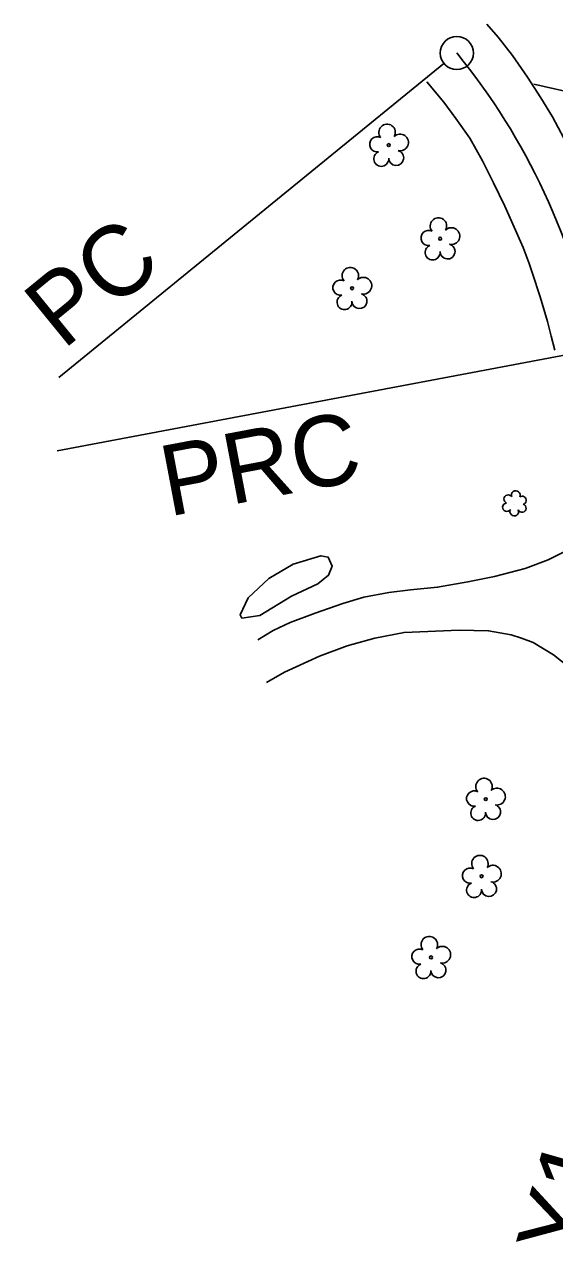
# Model space of a CAD drawing. Extents: x 479429 to 482809, y 488118 to 492379.
# Drawn here: x 481001.5 to 481121.6, y 490861 to 491136.5 of the extents above; entities that cross this region are included whole.
import ezdxf

# ---------------------------------------------------------------- set-up
doc = ezdxf.new("R2010")
doc.units = 0
for name, color, linetype in [('CTL Secondary Horizontal and Vertical Text', 7, 'Continuous'), ('Exist Horizontal Alignment', 7, 'Continuous'), ('Exist Other Culture Area Outline', 7, 'Continuous'), ('Exist Roads EOP', 7, 'Continuous'), ('Exist Roads EOP Other', 7, 'Continuous'), ('Exist Roads Soil', 7, 'Continuous'), ('Exist Vegetation Shrub CELL', 7, 'Continuous'), ('Exist Vegetation Tree CELL', 7, 'Continuous')]:
    doc.layers.add(name, color=color, linetype=linetype)

msp = doc.modelspace()

# ---------------------------------------------------------------- linework, layer by layer
at = {"layer": 'Exist Horizontal Alignment'}
for p, q in [((481096.5, 491127.64), (481009.35, 491056.54)), ((481126.93, 491062.26), (481008.98, 491039.95))]:
    msp.add_line(p, q, dxfattribs=at)
msp.add_circle((481099.4, 491130.01), 3.75, dxfattribs=at)
msp.add_arc((480982.98, 491035.04), 150.25, 10.7112, 39.2065, dxfattribs=at)
at = {"layer": 'Exist Other Culture Area Outline'}
msp.add_lwpolyline([(481050.74, 491002.12), (481054.81, 491002.71), (481062, 491007.11), (481067.93, 491009.89), (481070.39, 491011.8), (481071.17, 491013.86), (481070.32, 491015.9), (481068.66, 491016.25), (481062.35, 491014.35), (481056.83, 491011.06), (481052.16, 491006.67), (481050.34, 491002.89), (481050.74, 491002.12)], dxfattribs=at)
at = {"layer": 'Exist Roads EOP'}
for points in [[(481106.2, 491136.5), (481108.79, 491133.61), (481112.05, 491129.43), (481115.42, 491124.55), (481118.46, 491119.89), (481121.04, 491115.59), (481123.64, 491110.73)], [(481121.63, 491062.76), (481120.8, 491065.9), (481119.9, 491069.23), (481118.24, 491074.84), (481116.55, 491080.1), (481115.77, 491082.39), (481114.41, 491086.02), (481112.12, 491091.28), (481110.25, 491095.36), (481107.69, 491100.66), (481105.2, 491105.64), (481102.33, 491110.73), (481099.21, 491115.21), (481096.44, 491118.92), (481092.61, 491123.52)]]:
    msp.add_lwpolyline(points, dxfattribs=at)
at = {"layer": 'Exist Roads EOP Other'}
for points in [[(481054.34, 490997.22), (481057.87, 490999.28), (481061.71, 491001.13), (481067.32, 491003.23), (481073.64, 491005.42), (481078.33, 491006.84), (481084.04, 491007.88), (481088.9, 491008.51), (481095.04, 491009.09), (481101.93, 491010.32), (481107.91, 491011.53), (481114.89, 491013.32), (481120.11, 491015.29), (481124.02, 491017.3), (481125.95, 491019.67), (481127.35, 491022.46), (481127.62, 491023.23), (481128.62, 491026.47)], [(481149.23, 490952.04), (481145.81, 490955.42), (481142.2, 490959.44), (481138.39, 490965.71), (481133.32, 490977.24), (481127.4, 490987.65), (481124.91, 490990.93), (481121.32, 490993.83), (481116.71, 490996.59), (481114.03, 490997.59), (481111.68, 490998.3), (481106.61, 490999.24), (481099.92, 490999.38), (481087.46, 490998.88), (481080.89, 490997.59), (481074.58, 490995.84), (481068.34, 490993.5), (481060.39, 490989.91), (481056.37, 490987.51)]]:
    msp.add_lwpolyline(points, dxfattribs=at)
at = {"layer": 'Exist Roads Soil'}
msp.add_lwpolyline([(481116.84, 491122.97), (481129.2, 491120.2), (481146.03, 491116.72), (481180.59, 491108.8), (481206.93, 491101.17)], dxfattribs=at)
at = {"layer": 'Exist Vegetation Shrub CELL'}
msp.add_line((481112.53, 491027.92), (481112.53, 491027.92), dxfattribs=at)
for centre, radius, start, end in [((481112.76, 491029.96), 0.99, 334.8391, 200.4717), ((481110.73, 491027.21), 0.955, 95.1099, 327.9534), ((481111.05, 491029.04), 0.968, 35.8908, 245.4216), ((481114.17, 491026.99), 0.937, 204.9913, 73.4601), ((481114.21, 491028.78), 0.929, 284.4567, 126.0861), ((481112.41, 491026.23), 0.984, 151.2797, 21.387)]:
    msp.add_arc(centre, radius, start, end, dxfattribs=at)
at = {"layer": 'Exist Vegetation Tree CELL'}
for p, q in [((481084.01, 491109.17), (481084.01, 491109.17)), ((481095.63, 491087.99), (481095.63, 491087.99)), ((481075.7, 491076.76), (481075.7, 491076.76)), ((481105.95, 490961.13), (481105.95, 490961.13)), ((481105.02, 490943.7), (481105.02, 490943.7)), ((481093.57, 490925.34), (481093.57, 490925.34))]:
    msp.add_line(p, q, dxfattribs=at)
for centre in [(481084.01, 491109.17), (481095.63, 491087.99), (481075.7, 491076.76), (481105.95, 490961.13), (481105.02, 490943.7), (481093.57, 490925.34)]:
    msp.add_circle(centre, 0.326, dxfattribs=at)
for centre, radius, start, end in [((481083.63, 491112.05), 1.86, 330.1651, 219.7134), ((481081.41, 491109.33), 1.73, 62.6636, 279.3457), ((481086.56, 491109.76), 1.9, 257.1011, 134.1999), ((481085.69, 491106.27), 1.7, 181.2822, 74.56), ((481082.31, 491106.05), 1.69, 111.5671, 6.231), ((481095.25, 491090.86), 1.86, 330.1651, 219.7134), ((481093.03, 491088.14), 1.73, 62.6636, 279.3457), ((481098.18, 491088.58), 1.9, 257.1011, 134.1999), ((481093.93, 491084.87), 1.69, 111.5671, 6.231), ((481097.31, 491085.09), 1.7, 181.2822, 74.56), ((481075.31, 491079.63), 1.86, 330.1651, 219.7134), ((481073.09, 491076.91), 1.73, 62.6636, 279.3457), ((481078.25, 491077.34), 1.9, 257.1011, 134.1999), ((481073.99, 491073.63), 1.69, 111.5671, 6.231), ((481077.37, 491073.86), 1.7, 181.2822, 74.56), ((481105.56, 490964.01), 1.86, 330.1651, 219.7134), ((481103.34, 490961.29), 1.73, 62.6636, 279.3457), ((481108.5, 490961.72), 1.9, 257.1011, 134.1999), ((481104.25, 490958.01), 1.69, 111.5671, 6.231), ((481107.62, 490958.23), 1.7, 181.2822, 74.56), ((481104.64, 490946.57), 1.86, 330.1651, 219.7134), ((481102.42, 490943.85), 1.73, 62.6636, 279.3457), ((481107.57, 490944.28), 1.9, 257.1011, 134.1999), ((481106.7, 490940.8), 1.7, 181.2822, 74.56), ((481103.32, 490940.57), 1.69, 111.5671, 6.231), ((481093.18, 490928.22), 1.86, 330.1651, 219.7134), ((481090.96, 490925.5), 1.73, 62.6636, 279.3457), ((481096.12, 490925.93), 1.9, 257.1011, 134.1999), ((481091.86, 490922.22), 1.69, 111.5671, 6.231), ((481095.24, 490922.44), 1.7, 181.2822, 74.56)]:
    msp.add_arc(centre, radius, start, end, dxfattribs=at)

# ---------------------------------------------------------------- texts
at = {"layer": 'CTL Secondary Horizontal and Vertical Text'}
msp.add_text('BY1-127', height=16, rotation=73.904, dxfattribs=at).set_placement((481124.08, 490842.35))
at = {"layer": 'Exist Horizontal Alignment'}
for s, rotation, p in [('PC', 39.2065, (481010.28, 491062.66)), ('PRC', 10.7112, (481034.17, 491025.07))]:
    msp.add_text(s, height=16, rotation=rotation, dxfattribs=at).set_placement(p)

doc.saveas('drawing.dxf')
